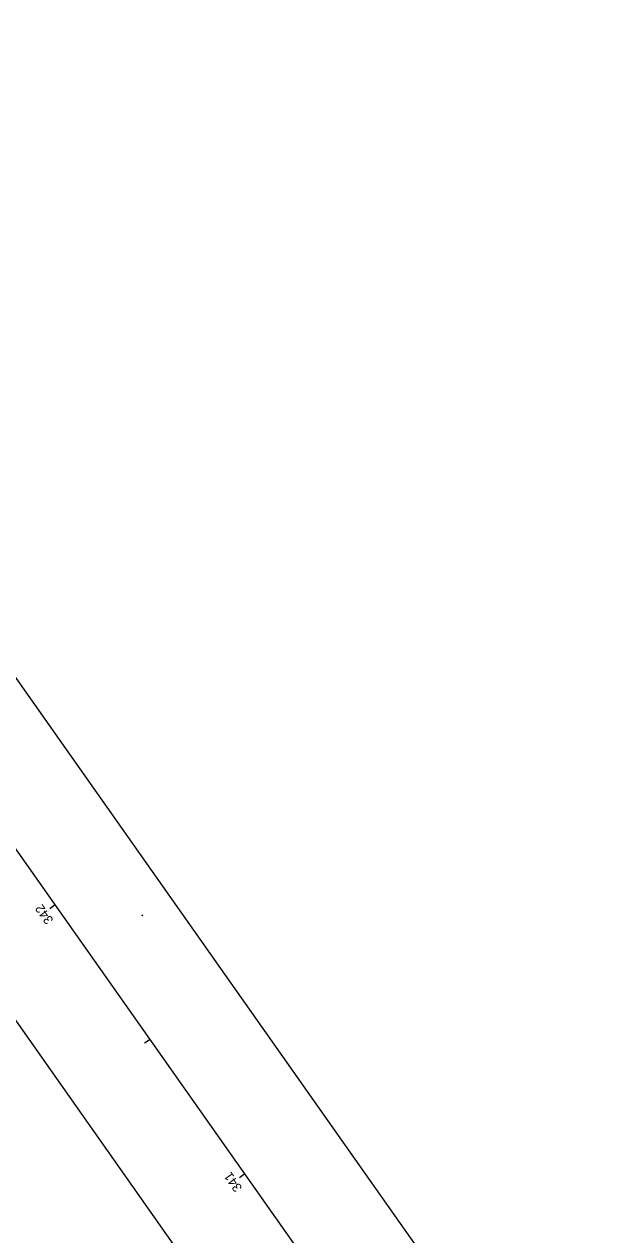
# Model space of a CAD drawing. Extents: x 1345023 to 1351589, y 535029 to 544731.
# Drawn here: x 1346043.6 to 1346222, y 543612.4 to 543980.2 of the extents above; entities that cross this region are included whole.
import ezdxf

# ---------------------------------------------------------------- set-up
doc = ezdxf.new("R2010")
doc.units = 0
for name, color, linetype in [('Default', 7, 'Continuous'), ('GE_X_CL_20', 7, 'Continuous'), ('RW_X_CL_20', 7, 'Continuous'), ('RW_X_Esmt_SH', 7, 'Continuous'), ('SV_P_Control_Cells_Set', 7, 'Continuous'), ('SV_X_Text_Elevation', 7, 'Continuous'), ('SV_X_Text_Name', 7, 'Continuous')]:
    doc.layers.add(name, color=color, linetype=linetype)

msp = doc.modelspace()

# ---------------------------------------------------------------- linework, layer by layer
at = {"layer": 'Default'}
msp.add_circle((1346078.94, 543674.9), 1056.04, dxfattribs=at)
at = {"layer": 'GE_X_CL_20'}
for p, q in [((1346053.04, 543712.62), (1346051.41, 543711.46)), ((1346081.87, 543671.76), (1346080.23, 543670.61)), ((1346110.69, 543630.91), (1346109.06, 543629.76))]:
    msp.add_line(p, q, dxfattribs=at)
at = {"layer": 'RW_X_CL_20'}
msp.add_line((1348162.36, 540723.41), (1345880.07, 543957.73), dxfattribs=at)
msp.add_line((1348162.36, 540723.41), (1345880.07, 543957.73), dxfattribs=at)
at = {"layer": 'RW_X_Esmt_SH'}
for p, q in [((1348186.89, 540740.69), (1345904.58, 543975.03)), ((1348137.84, 540706.13), (1345855.56, 543940.44))]:
    msp.add_line(p, q, dxfattribs=at)
at = {"layer": 'SV_P_Control_Cells_Set'}
for points in [[(1346079.36, 543709.4), (1346079.36, 543709.48), (1346079.39, 543709.4), (1346079.41, 543709.48), (1346079.41, 543709.4)], [(1346079.45, 543709.41), (1346079.45, 543709.41), (1346079.46, 543709.41), (1346079.46, 543709.41), (1346079.46, 543709.41), (1346079.46, 543709.4), (1346079.45, 543709.4), (1346079.45, 543709.4), (1346079.45, 543709.4), (1346079.45, 543709.41), (1346079.45, 543709.41), (1346079.45, 543709.41), (1346079.45, 543709.41)], [(1346079.48, 543709.4), (1346079.48, 543709.48), (1346079.52, 543709.4), (1346079.52, 543709.48)], [(1346079.56, 543709.41), (1346079.57, 543709.41), (1346079.57, 543709.41), (1346079.57, 543709.41), (1346079.57, 543709.41), (1346079.57, 543709.4), (1346079.57, 543709.4), (1346079.56, 543709.4), (1346079.56, 543709.4), (1346079.56, 543709.41), (1346079.56, 543709.41), (1346079.56, 543709.41), (1346079.56, 543709.41)], [(1346079.63, 543709.48), (1346079.63, 543709.48), (1346079.63, 543709.48), (1346079.62, 543709.48), (1346079.62, 543709.48), (1346079.61, 543709.48), (1346079.61, 543709.48), (1346079.6, 543709.48), (1346079.6, 543709.48), (1346079.59, 543709.47), (1346079.59, 543709.47), (1346079.59, 543709.46), (1346079.59, 543709.46), (1346079.6, 543709.45), (1346079.63, 543709.44), (1346079.63, 543709.43), (1346079.63, 543709.43), (1346079.63, 543709.43), (1346079.63, 543709.42), (1346079.63, 543709.42), (1346079.63, 543709.42), (1346079.63, 543709.41), (1346079.63, 543709.41), (1346079.63, 543709.41), (1346079.63, 543709.41), (1346079.63, 543709.41), (1346079.62, 543709.4), (1346079.62, 543709.4), (1346079.62, 543709.4), (1346079.61, 543709.4), (1346079.6, 543709.4), (1346079.6, 543709.41), (1346079.59, 543709.41)], [(1346079.67, 543709.41), (1346079.67, 543709.41), (1346079.68, 543709.41), (1346079.68, 543709.41), (1346079.68, 543709.41), (1346079.68, 543709.4), (1346079.67, 543709.4), (1346079.67, 543709.4), (1346079.67, 543709.4), (1346079.67, 543709.41), (1346079.67, 543709.41), (1346079.67, 543709.41), (1346079.67, 543709.41)]]:
    msp.add_lwpolyline(points, dxfattribs=at)
msp.add_circle((1346079.26, 543709.44), 0.0249, dxfattribs=at)

# ---------------------------------------------------------------- texts
at = {"layer": 'GE_X_CL_20'}
for s, p in [('342', (1346052.61, 543708.02)), ('341', (1346110, 543626.7))]:
    msp.add_text(s, height=2.8, rotation=125.2086, dxfattribs=at).set_placement(p)
at = {"layer": 'SV_X_Text_Elevation'}
msp.add_text('861.01', height=0.06, dxfattribs=at).set_placement((1346079.02, 543709.38))
at = {"layer": 'SV_X_Text_Name'}
msp.add_text('FV3', height=0.06, dxfattribs=at).set_placement((1346079.12, 543709.44))

doc.saveas('drawing.dxf')
